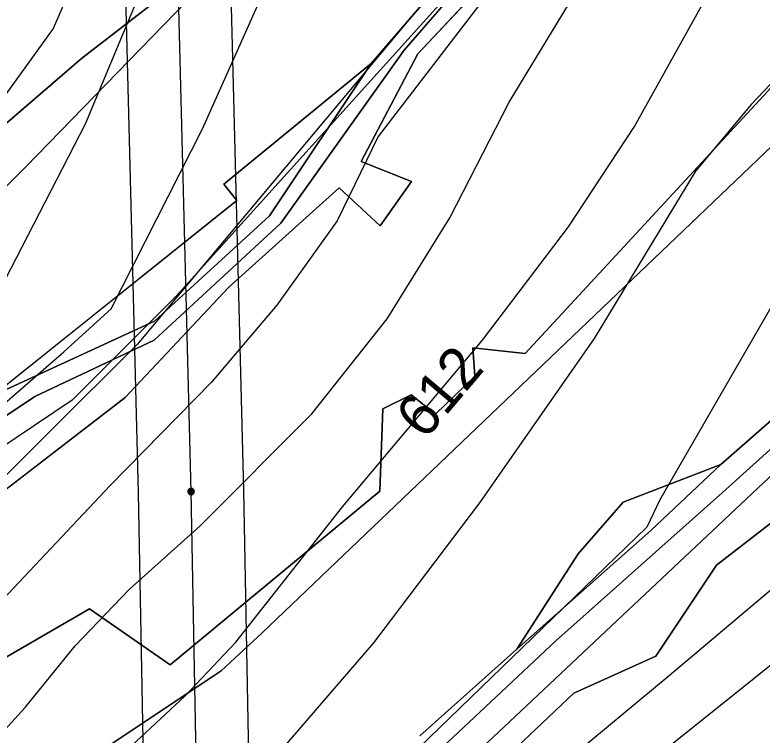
# Model space of a CAD drawing. Extents: x -709418 to -703832, y -1161719 to -1157826.
# Drawn here: x -706924.1 to -706782.1, y -1159816.4 to -1159679.5 of the extents above; entities that cross this region are included whole.
import ezdxf

# ---------------------------------------------------------------- set-up
doc = ezdxf.new("R2010")
doc.units = 0
for name, color, linetype in [('106_zastavitelné plochy', 7, 'Continuous'), ('120_vrstevnice hlavní', 7, 'Continuous'), ('121_vrstevnice hlavní_popis', 7, 'Continuous'), ('122_vrstevnice základní', 7, 'Continuous'), ('201_orná půda_KN', 7, 'Continuous'), ('206_TTP_KN', 7, 'Continuous'), ('210_ostatní plocha_KN', 7, 'Continuous'), ('705_el VN nadzemní_E.ON', 7, 'Continuous'), ('735_OP sítí TI', 7, 'Continuous')]:
    doc.layers.add(name, color=color, linetype=linetype)

# ---------------------------------------------------------------- blocks, each defined once
blk = doc.blocks.new('Elektro - Implicitní$0$VN4601')
for points in [[(1.23, 0), (1.22, 0.13), (1.2, 0.26), (1.17, 0.38), (1.12, 0.5), (1.06, 0.61), (0.99, 0.72), (0.91, 0.82), (0.82, 0.91), (0.72, 0.99), (0.61, 1.06), (0.5, 1.12), (0.38, 1.17), (0.26, 1.2), (0.13, 1.22), (0, 1.23), (-0.13, 1.22), (-0.26, 1.2), (-0.38, 1.17), (-0.5, 1.12), (-0.61, 1.06), (-0.72, 0.99), (-0.82, 0.91), (-0.91, 0.82), (-0.99, 0.72), (-1.06, 0.61), (-1.12, 0.5), (-1.17, 0.38), (-1.2, 0.26), (-1.22, 0.13), (-1.23, 0), (-1.22, -0.13), (-1.2, -0.26), (-1.17, -0.38), (-1.12, -0.5), (-1.06, -0.61), (-0.99, -0.72), (-0.91, -0.82), (-0.82, -0.91), (-0.72, -0.99), (-0.61, -1.06), (-0.5, -1.12), (-0.38, -1.17), (-0.26, -1.2), (-0.13, -1.22), (0, -1.23), (0.13, -1.22), (0.26, -1.2), (0.38, -1.17), (0.5, -1.12), (0.61, -1.06), (0.72, -0.99), (0.82, -0.91), (0.91, -0.82), (0.99, -0.72), (1.06, -0.61), (1.12, -0.5), (1.17, -0.38), (1.2, -0.26), (1.22, -0.13), (1.23, 0)], [(0.92, 0), (0.92, 0.1), (0.9, 0.19), (0.88, 0.28), (0.84, 0.37), (0.8, 0.46), (0.75, 0.54), (0.68, 0.62), (0.62, 0.68), (0.54, 0.74), (0.46, 0.8), (0.37, 0.84), (0.28, 0.88), (0.19, 0.9), (0.1, 0.92), (0, 0.92), (-0.1, 0.92), (-0.19, 0.9), (-0.28, 0.88), (-0.37, 0.84), (-0.46, 0.8), (-0.54, 0.74), (-0.62, 0.68), (-0.68, 0.62), (-0.75, 0.54), (-0.8, 0.46), (-0.84, 0.37), (-0.88, 0.28), (-0.9, 0.19), (-0.92, 0.1), (-0.92, 0), (-0.92, -0.1), (-0.9, -0.19), (-0.88, -0.29), (-0.84, -0.38), (-0.8, -0.46), (-0.75, -0.54), (-0.68, -0.62), (-0.62, -0.69), (-0.54, -0.75), (-0.46, -0.8), (-0.37, -0.84), (-0.28, -0.88), (-0.19, -0.9), (-0.1, -0.92), (0, -0.92), (0.1, -0.92), (0.19, -0.9), (0.28, -0.88), (0.37, -0.84), (0.46, -0.8), (0.54, -0.75), (0.62, -0.69), (0.68, -0.62), (0.75, -0.54), (0.8, -0.46), (0.84, -0.38), (0.88, -0.29), (0.9, -0.19), (0.92, -0.1), (0.92, 0)], [(0.61, 0), (0.61, 0.06), (0.6, 0.13), (0.58, 0.19), (0.56, 0.25), (0.53, 0.31), (0.5, 0.36), (0.46, 0.41), (0.41, 0.46), (0.36, 0.5), (0.31, 0.53), (0.25, 0.56), (0.19, 0.58), (0.13, 0.6), (0.06, 0.61), (0, 0.61), (-0.06, 0.61), (-0.13, 0.6), (-0.19, 0.58), (-0.25, 0.56), (-0.31, 0.53), (-0.36, 0.5), (-0.41, 0.46), (-0.46, 0.41), (-0.5, 0.36), (-0.53, 0.31), (-0.56, 0.25), (-0.58, 0.19), (-0.6, 0.13), (-0.61, 0.06), (-0.61, 0), (-0.61, -0.07), (-0.6, -0.13), (-0.58, -0.19), (-0.56, -0.25), (-0.53, -0.31), (-0.5, -0.36), (-0.46, -0.41), (-0.41, -0.46), (-0.36, -0.5), (-0.31, -0.53), (-0.25, -0.56), (-0.19, -0.58), (-0.13, -0.6), (-0.06, -0.61), (0, -0.61), (0.06, -0.61), (0.13, -0.6), (0.19, -0.58), (0.25, -0.56), (0.31, -0.53), (0.36, -0.5), (0.41, -0.46), (0.46, -0.41), (0.5, -0.36), (0.53, -0.31), (0.56, -0.25), (0.58, -0.19), (0.6, -0.13), (0.61, -0.06), (0.61, 0)], [(0.31, 0), (0.31, 0.03), (0.3, 0.06), (0.29, 0.09), (0.28, 0.12), (0.27, 0.15), (0.25, 0.18), (0.23, 0.21), (0.21, 0.23), (0.18, 0.25), (0.15, 0.27), (0.12, 0.28), (0.09, 0.29), (0.06, 0.3), (0.03, 0.31), (0, 0.31), (-0.03, 0.31), (-0.06, 0.3), (-0.09, 0.29), (-0.12, 0.28), (-0.15, 0.27), (-0.18, 0.25), (-0.21, 0.23), (-0.23, 0.21), (-0.25, 0.18), (-0.27, 0.15), (-0.28, 0.12), (-0.29, 0.09), (-0.3, 0.06), (-0.31, 0.03), (-0.31, 0), (-0.31, -0.03), (-0.3, -0.06), (-0.29, -0.1), (-0.28, -0.13), (-0.27, -0.15), (-0.25, -0.18), (-0.23, -0.21), (-0.21, -0.23), (-0.18, -0.25), (-0.15, -0.27), (-0.12, -0.28), (-0.09, -0.29), (-0.06, -0.3), (-0.03, -0.31), (0, -0.31), (0.03, -0.31), (0.06, -0.3), (0.09, -0.29), (0.12, -0.28), (0.15, -0.27), (0.18, -0.25), (0.21, -0.23), (0.23, -0.21), (0.25, -0.18), (0.27, -0.15), (0.28, -0.13), (0.29, -0.1), (0.3, -0.06), (0.31, -0.03), (0.31, 0)]]:
    blk.add_lwpolyline(points)

msp = doc.modelspace()

# ---------------------------------------------------------------- linework, layer by layer
at = {"layer": '106_zastavitelné plochy'}
for points in [[(-706699.08, -1159526.92), (-706830.66, -1159663.21), (-706893.51, -1159732.95), (-706913.28, -1159752.71), (-706948.73, -1159776.56), (-707000.54, -1159797.01), (-706999.86, -1159788.83), (-706998.55, -1159782.52), (-706991.13, -1159778.66), (-706993.63, -1159771.46), (-706950.95, -1159752.19), (-706963.59, -1159730.93), (-707001.32, -1159748.1), (-707016.41, -1159753.81), (-707020.99, -1159741.13), (-707003.27, -1159724.77), (-706948.05, -1159693.43), (-706937.82, -1159711.14), (-706958.96, -1159723.41), (-706952.14, -1159732.27), (-706932.37, -1159718.64), (-706922.06, -1159708.33)], [(-706922.06, -1159708.33), (-706878.43, -1159663.36), (-706813.66, -1159590.44), (-706782.3, -1159546.83)]]:
    msp.add_lwpolyline(points, dxfattribs=at)
at = {"layer": '120_vrstevnice hlavní'}
for points in [[(-706974.01, -1159913.97), (-706959.5, -1159902.65), (-706957.59, -1159896.67), (-706956.45, -1159887.7), (-706956.19, -1159861.76), (-706952.74, -1159850.24), (-706950.29, -1159844.74), (-706946.96, -1159839.25), (-706942.77, -1159833.75), (-706922.22, -1159811.18), (-706912.68, -1159799.47), (-706902.41, -1159788.76), (-706888.96, -1159776.61), (-706867.7, -1159755.35), (-706853.38, -1159737.27), (-706841.51, -1159718.03), (-706830.23, -1159696.05), (-706813.74, -1159668.85), (-706808.97, -1159658.44), (-706803.33, -1159642.67), (-706770.56, -1159605.48)], [(-706899.32, -1159638.99), (-706904.61, -1159651.22), (-706908.92, -1159663.65), (-706916.87, -1159682.02), (-706945.07, -1159721.09), (-706950.09, -1159731.18), (-706952.54, -1159739.35), (-706956.02, -1159749.01)], [(-706753.27, -1159765.73), (-706777.93, -1159786.73), (-706799.82, -1159805.13), (-706817.65, -1159820.01), (-706848.89, -1159847.78), (-706867.26, -1159866.15), (-706879.41, -1159881.48), (-706886.35, -1159893.34), (-706891.85, -1159904.62), (-706906.45, -1159940.48), (-706914.64, -1159958.98), (-706920.42, -1159968.23), (-706927.19, -1159976.29)]]:
    msp.add_lwpolyline(points, dxfattribs=at)
at = {"layer": '122_vrstevnice základní'}
for points in [[(-706794.58, -1159572.43), (-706796.07, -1159577.85), (-706797.41, -1159586.38), (-706798.12, -1159608.68), (-706798.7, -1159622.57), (-706799.57, -1159630.23), (-706855.11, -1159702.56)], [(-706952.21, -1159904.95), (-706947.42, -1159896.51), (-706940.55, -1159881.92), (-706933.99, -1159865.49), (-706929.6, -1159854.58), (-706922.8, -1159840.69), (-706915.86, -1159831.43), (-706891.85, -1159809.01), (-706882.16, -1159798.74), (-706861.91, -1159773), (-706835.29, -1159741.32), (-706818.95, -1159719.77), (-706806.36, -1159700.68), (-706784.09, -1159660.47), (-706779.32, -1159648.89), (-706762.97, -1159614.18), (-706754.58, -1159600.29), (-706742.72, -1159583.95), (-706739.13, -1159579.22)], [(-706711.29, -1159582.62), (-706716.52, -1159590.02), (-706729.27, -1159617.65), (-706732.89, -1159629.22), (-706746.19, -1159652.36), (-706753.72, -1159663.36), (-706766.04, -1159678), (-706772.09, -1159683.75), (-706784.23, -1159696.48), (-706794.79, -1159709.21), (-706814.03, -1159741.03), (-706835.87, -1159772.28), (-706855.98, -1159798.89), (-706881.31, -1159828.32), (-706900.74, -1159847.56), (-706912.26, -1159860.91), (-706920.62, -1159874.81), (-706930.78, -1159890.2), (-706937.79, -1159902.61)], [(-706681.49, -1159586.27), (-706692.4, -1159595.86), (-706700.63, -1159606.08), (-706705.11, -1159613.6), (-706708.3, -1159620.54), (-706722.47, -1159643.25), (-706725.51, -1159649.33), (-706727.39, -1159651.64), (-706750.1, -1159688.24), (-706759.07, -1159700.82), (-706772.95, -1159722.08), (-706801.59, -1159771.7), (-706804.05, -1159776.9), (-706918.39, -1159887.65)], [(-706660.95, -1159588.78), (-706676.91, -1159603.19), (-706687.32, -1159613.74), (-706694.12, -1159622.42), (-706699.76, -1159630.81), (-706708.3, -1159647.59), (-706720.59, -1159678.69), (-706732.31, -1159705.02), (-706739.83, -1159719.19), (-706748.51, -1159733.94), (-706757.19, -1159745.23), (-706856.87, -1159839.1), (-706882.04, -1159862.88)], [(-706824.32, -1159592.45), (-706824.73, -1159610.13), (-706831.1, -1159635.59), (-706836.89, -1159654.1), (-706844.41, -1159674.5), (-706900.91, -1159742.16)], [(-706960.82, -1159783.52), (-706914.82, -1159743.55), (-706905.88, -1159735.39), (-706888.52, -1159701.16), (-706874.35, -1159669.43), (-706859.16, -1159631.68)], [(-706901.17, -1159677.14), (-706910.8, -1159700.24), (-706935.97, -1159748.99), (-706942.48, -1159760.41), (-706967.57, -1159781.44), (-706984.86, -1159798.1)], [(-706855.11, -1159702.56), (-706862.92, -1159718.61), (-706874.35, -1159734.67), (-706886.79, -1159749.28), (-706906.03, -1159768.95), (-706929.6, -1159793.97), (-706944.65, -1159813.64), (-706963.31, -1159839.68), (-706968.22, -1159848.36), (-706970.83, -1159854.29), (-706974.01, -1159864.7), (-706976.47, -1159880.32), (-706976.9, -1159888.14), (-706975.74, -1159906.51)], [(-706997.58, -1159915.33), (-706999.1, -1159902.36), (-706997.88, -1159885.82), (-706996.72, -1159878.88), (-706994.84, -1159871.94), (-706989.05, -1159855.74), (-706964.46, -1159814.08), (-706955.06, -1159799.76), (-706934.23, -1159775.31), (-706900.91, -1159742.16)], [(-706721.94, -1159748.41), (-706730.6, -1159760.82), (-706742.26, -1159771.6), (-706754.76, -1159782.56), (-706811.57, -1159828.03), (-706847.73, -1159861.09), (-706860.96, -1159878.05), (-706870.48, -1159893.22), (-706876.33, -1159907.78), (-706883.32, -1159925.2), (-706890.86, -1159941.57), (-706899.72, -1159957.09)]]:
    msp.add_lwpolyline(points, dxfattribs=at)
at = {"layer": '201_orná půda_KN'}
for p, q in [((-706877.13, -1159796.96), (-706773.77, -1159698.16)), ((-706766.24, -1159744.08), (-706789.95, -1159764.97)), ((-706789.95, -1159764.97), (-706808.54, -1159772.12)), ((-706808.54, -1159772.12), (-706817.1, -1159781.99)), ((-706817.1, -1159781.99), (-706828.75, -1159800.1)), ((-706884.94, -1159804.2), (-706877.13, -1159796.96)), ((-706828.75, -1159800.1), (-706847.16, -1159816.58)), ((-706943.1, -1159842.98), (-706884.94, -1159804.2))]:
    msp.add_line(p, q, dxfattribs=at)
at = {"layer": '206_TTP_KN'}
for p, q in [((-706847.54, -1159686.9), (-706814.32, -1159651.33)), ((-706858.34, -1159707.34), (-706847.54, -1159686.9)), ((-706777.45, -1159690.03), (-706827.14, -1159743.87)), ((-706848.75, -1159711.16), (-706858.34, -1159707.34)), ((-706854.71, -1159719.55), (-706848.75, -1159711.16)), ((-706883.47, -1159731.27), (-706862.52, -1159712.38)), ((-706862.52, -1159712.38), (-706854.71, -1159719.55)), ((-706903.21, -1159752.22), (-706883.47, -1159731.27)), ((-706827.14, -1159743.87), (-706837.13, -1159742.76)), ((-706837.13, -1159742.76), (-706836.74, -1159748.15)), ((-706836.74, -1159748.15), (-706844.23, -1159755.39)), ((-706943.74, -1159783.47), (-706903.21, -1159752.22)), ((-706848.8, -1159751.75), (-706854.22, -1159754.36)), ((-706844.23, -1159755.39), (-706848.8, -1159751.75)), ((-706854.22, -1159754.36), (-706854.79, -1159770.02)), ((-706790.82, -1159784.11), (-706761.18, -1159761.18)), ((-706854.79, -1159770.02), (-706894.65, -1159803.09)), ((-706802.31, -1159801.45), (-706790.82, -1159784.11)), ((-706909.99, -1159792.43), (-706948.67, -1159814.84)), ((-706894.65, -1159803.09), (-706909.99, -1159792.43)), ((-706817.94, -1159808.45), (-706802.31, -1159801.45)), ((-706877.31, -1159864.82), (-706817.94, -1159808.45))]:
    msp.add_line(p, q, dxfattribs=at)
for points in [[(-706721.06, -1159545.49), (-706740.27, -1159565.63), (-706756.5, -1159581.55), (-706767.24, -1159593.33), (-706781.02, -1159608.89), (-706790.51, -1159618.63), (-706810.49, -1159637.54), (-706816.48, -1159644.1), (-706830.18, -1159659.38), (-706841.14, -1159670.97), (-706856.43, -1159688.73), (-706884.45, -1159711.66), (-706881.99, -1159714.76), (-706928.31, -1159751.83), (-706947.58, -1159727.78), (-706955.37, -1159734.01), (-706953.1, -1159741.94), (-706941.64, -1159737.83), (-706937.01, -1159750), (-706948.87, -1159756.5), (-706991.13, -1159778.66), (-706993.63, -1159771.46)], [(-706993.63, -1159771.46), (-706950.95, -1159752.19), (-706963.59, -1159730.93), (-706956.25, -1159725.98), (-706936.86, -1159709.56), (-706911.52, -1159687.76), (-706884.5, -1159666.84), (-706849.25, -1159621.1), (-706827.2, -1159598.19), (-706815.42, -1159598.62), (-706807.57, -1159590.13), (-706811.57, -1159580.5), (-706787.66, -1159545.74)]]:
    msp.add_lwpolyline(points, dxfattribs=at)
at = {"layer": '210_ostatní plocha_KN'}
for p, q in [((-706832.43, -1159665.69), (-706850.16, -1159686.17)), ((-706856.43, -1159688.73), (-706841.14, -1159670.97)), ((-706850.16, -1159686.17), (-706873.58, -1159719.08)), ((-706884.45, -1159711.66), (-706856.43, -1159688.73)), ((-706875.77, -1159717.7), (-706856.43, -1159688.73)), ((-706856.43, -1159688.73), (-706875.77, -1159717.7)), ((-706827.14, -1159743.87), (-706777.45, -1159690.03)), ((-706773.77, -1159698.16), (-706877.13, -1159796.96)), ((-706881.99, -1159714.76), (-706884.45, -1159711.66)), ((-706928.31, -1159751.83), (-706881.99, -1159714.76)), ((-706897.59, -1159737.74), (-706875.77, -1159717.7)), ((-706875.77, -1159717.7), (-706897.59, -1159737.74)), ((-706873.58, -1159719.08), (-706897.66, -1159741.34)), ((-706928.31, -1159751.83), (-706897.59, -1159737.74)), ((-706897.59, -1159737.74), (-706928.31, -1159751.83)), ((-706897.66, -1159741.34), (-706920.36, -1159752.04)), ((-706836.74, -1159748.15), (-706837.13, -1159742.76)), ((-706837.13, -1159742.76), (-706827.14, -1159743.87)), ((-706789.95, -1159764.97), (-706766.24, -1159744.08)), ((-706844.23, -1159755.39), (-706836.74, -1159748.15)), ((-706765.82, -1159748.69), (-706789.63, -1159770.3)), ((-706789.63, -1159770.3), (-706765.82, -1159748.69)), ((-706920.36, -1159752.04), (-706947.33, -1159770.09)), ((-706854.22, -1159754.36), (-706848.8, -1159751.75)), ((-706848.8, -1159751.75), (-706844.23, -1159755.39)), ((-706854.79, -1159770.02), (-706854.22, -1159754.36)), ((-706761.18, -1159761.18), (-706790.82, -1159784.11)), ((-706808.54, -1159772.12), (-706789.95, -1159764.97)), ((-706803.28, -1159777.49), (-706789.95, -1159764.97)), ((-706789.95, -1159764.97), (-706803.28, -1159777.49)), ((-706894.65, -1159803.09), (-706854.79, -1159770.02)), ((-706789.63, -1159770.3), (-706821.36, -1159798.53)), ((-706821.36, -1159798.53), (-706789.63, -1159770.3)), ((-706817.1, -1159781.99), (-706808.54, -1159772.12)), ((-706828.75, -1159800.1), (-706803.28, -1159777.49)), ((-706803.28, -1159777.49), (-706828.75, -1159800.1)), ((-706828.75, -1159800.1), (-706817.1, -1159781.99)), ((-706790.82, -1159784.11), (-706802.31, -1159801.45)), ((-706948.67, -1159814.84), (-706909.99, -1159792.43)), ((-706909.99, -1159792.43), (-706894.65, -1159803.09)), ((-706877.13, -1159796.96), (-706884.94, -1159804.2)), ((-706821.36, -1159798.53), (-706845.27, -1159820.93)), ((-706845.27, -1159820.93), (-706821.36, -1159798.53)), ((-706847.16, -1159816.58), (-706828.75, -1159800.1)), ((-706802.31, -1159801.45), (-706817.94, -1159808.45)), ((-706884.94, -1159804.2), (-706943.1, -1159842.98)), ((-706817.94, -1159808.45), (-706877.31, -1159864.82))]:
    msp.add_line(p, q, dxfattribs=at)
for points in [[(-706787.66, -1159545.74), (-706811.57, -1159580.5), (-706807.57, -1159590.13), (-706815.42, -1159598.62), (-706827.2, -1159598.19), (-706849.25, -1159621.1), (-706884.5, -1159666.84), (-706911.52, -1159687.76), (-706936.86, -1159709.56), (-706956.25, -1159725.98), (-706963.59, -1159730.93), (-707001.32, -1159748.1), (-707016.41, -1159753.81), (-707017.79, -1159754.47), (-707037.99, -1159764.1)], [(-707030.53, -1159806.03), (-707000.53, -1159794.22), (-706970.15, -1159778.64), (-706947.33, -1159770.09), (-706920.36, -1159752.04), (-706897.66, -1159741.34), (-706873.58, -1159719.08), (-706850.16, -1159686.17), (-706832.43, -1159665.69), (-706813.81, -1159645.42), (-706793.75, -1159626.94), (-706768.64, -1159603.54)], [(-706773.64, -1159610.72), (-706783.1, -1159623.07), (-706797.52, -1159636.2), (-706814.32, -1159651.33), (-706847.54, -1159686.9), (-706858.34, -1159707.34), (-706848.75, -1159711.16), (-706854.71, -1159719.55), (-706862.52, -1159712.38), (-706883.47, -1159731.27), (-706903.21, -1159752.22), (-706943.74, -1159783.47), (-707018.33, -1159813.43), (-707030.53, -1159806.03)]]:
    msp.add_lwpolyline(points, dxfattribs=at)
at = {"layer": '705_el VN nadzemní_E.ON'}
msp.add_lwpolyline([(-706880.73, -1160218.11), (-706883.24, -1160121.67), (-706885.97, -1160030.15), (-706888.81, -1159867.66), (-706890.66, -1159770.11), (-706893.19, -1159670.63), (-706895.78, -1159542.24), (-706897.96, -1159421.41), (-706883.28, -1159376.25), (-706867.82, -1159329.09), (-706796.05, -1159208.33), (-706732.4, -1159102.13), (-706682.71, -1159018.58)], dxfattribs=at)
at = {"layer": '735_OP sítí TI'}
for points in [[(-706890.9, -1160211.71), (-706893.24, -1160121.95), (-706895.97, -1160030.39), (-706898.81, -1159867.84), (-706900.66, -1159770.33), (-706903.19, -1159670.86), (-706905.78, -1159542.43), (-706907.99, -1159419.91), (-706892.79, -1159373.15), (-706876.98, -1159324.93), (-706804.64, -1159203.21), (-706740.99, -1159097), (-706691.31, -1159013.46)], [(-706870.8, -1160215.44), (-706873.24, -1160121.39), (-706875.97, -1160029.91), (-706878.81, -1159867.48), (-706880.66, -1159769.89), (-706883.19, -1159670.4), (-706885.78, -1159542.05), (-706887.93, -1159422.91), (-706873.77, -1159379.35), (-706858.66, -1159333.25), (-706787.46, -1159213.45), (-706723.81, -1159107.26), (-706674.12, -1159023.69)]]:
    msp.add_lwpolyline(points, dxfattribs=at)

# ---------------------------------------------------------------- block references
at = {"layer": '705_el VN nadzemní_E.ON', "xscale": 0.4999999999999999, "yscale": 0.49999999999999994, "rotation": -89.14143610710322}
msp.add_blockref('Elektro - Implicitní$0$VN4601', (-706890.66, -1159770.11), dxfattribs=at)

# ---------------------------------------------------------------- texts
at = {"layer": '121_vrstevnice hlavní_popis'}
msp.add_text('612', height=8, rotation=49.8459, dxfattribs=at).set_placement((-706846.21, -1159760.48))

doc.saveas('drawing.dxf')
